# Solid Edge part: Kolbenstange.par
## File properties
Username: bmolnar
Dokumentum tartalom típus: 0
Author: bmolnar
Last saved by: bmolnar
Revision: 83
Sűrűség: 0,000 kg/m^3
Pontosság: 0,990
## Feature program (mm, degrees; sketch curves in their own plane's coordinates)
base feature "unnamed BaseFeature 1"
sketch for "unnamed Protrusion 1" #1 plane through (21, 0.0012, 0) normal (1, 0, 0) x-axis (0, 1, 0)
  circle centre (-0.0012, 0) radius 3.2
sketch for "unnamed Protrusion 1" #2 plane through (21, 0.0012, 0) normal (1, 0, 0) x-axis (0, 1, 0)
  circle centre (-0.0012, 0) radius 8
extrude "unnamed Protrusion 1" add finite 11.1 along -normal
sketch for "Kihúzás_3" plane through (21, 0.0012, 0) normal (1, 0, 0) x-axis (0, 1, 0)
  circle centre (-0.0012, 0) radius 8
extrude "Kihúzás_3" add finite 4.5 along +normal
sketch for "Furat_1" plane through (-26, 0, 0.0012) normal (-1, 0, 0) x-axis (0, 0, -1)
  hole centre (0.0012, 0) bore radius 1.621
hole "Furat_1" nominal diameter 4 finite  ThreadDepth = 9 mm; StartChamferOffset = 0.3 mm; StartChamferAngle = 45 deg; VBottomAngle = 118 deg
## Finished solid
Body 1: solid body, 18 faces, 24 edges, 8 vertices.
  Faces by surface: plane 8, cylinder 5, cone 3, torus 2
  Edges by curve: circle 14, line 6, curve on surface 2, ellipse 2
Bounding box of the edges (mm; curved faces can reach further): 53.500 x 16.000 x 16.000, from (-28, -8, -8) to (25.5, 8, 8).
Cylindrical faces by radius (mm): R1.621 x2, R2.125 x1, R4 x1, R8 x1
Conical faces (half-angle, radius in mm at the cone's reference point): 45 deg R1.921 x1, 45 deg R2.225 x1, 59 deg R1.621 x1
Toroidal faces (ring radius, tube radius in mm): R1.925 r0.2 x1, R2.7 r1.3 x1
Planar faces by outward normal: +x 1, +z 1, -x 3, -z 1, oblique 2
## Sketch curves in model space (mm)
circle centre (21, 0, 0) radius 8
circle centre (21, 0, 0) radius 3.2
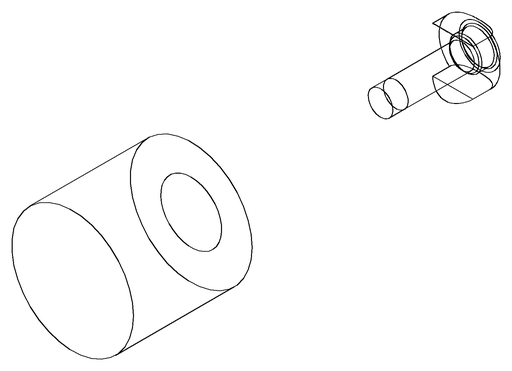
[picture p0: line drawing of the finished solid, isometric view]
